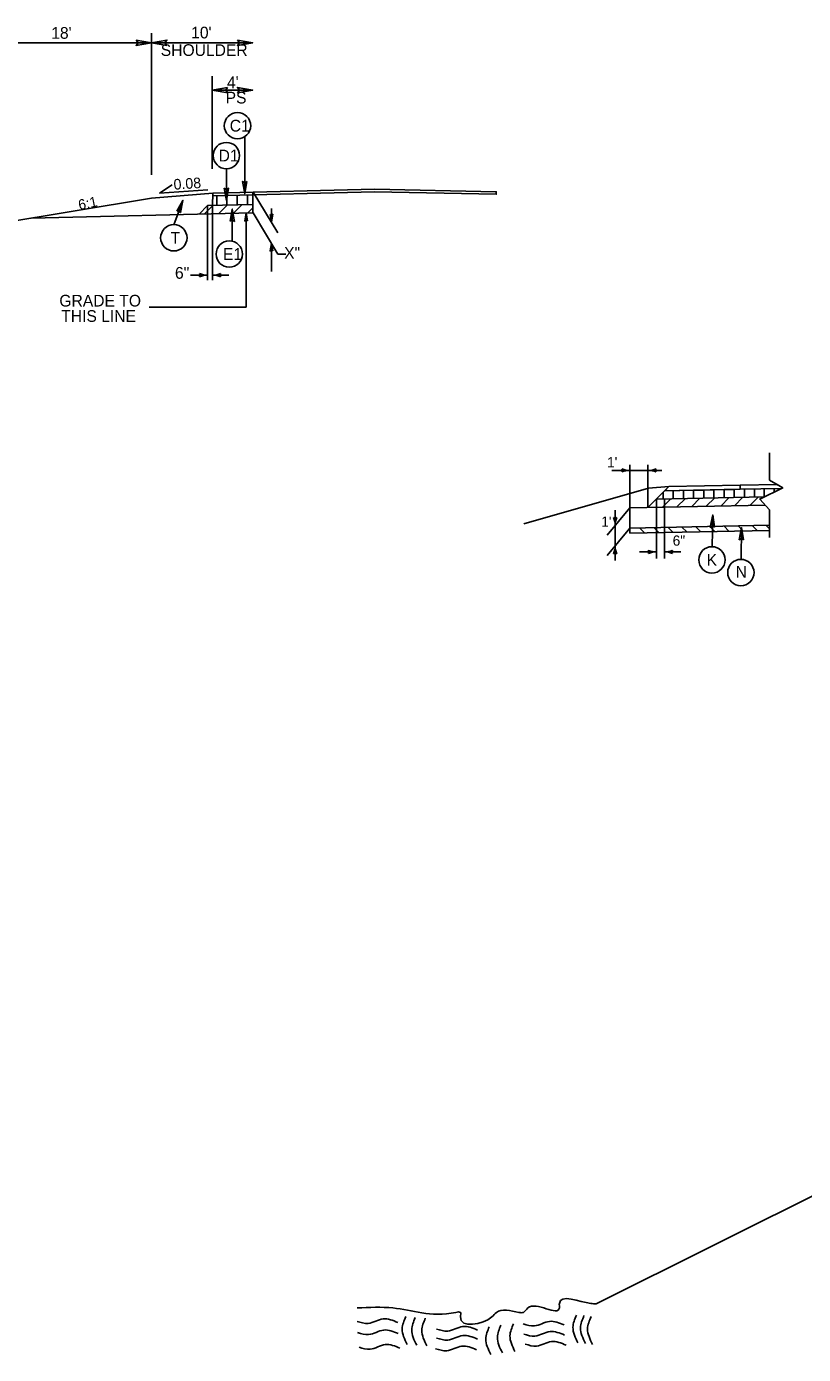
# Model space of a CAD drawing. Extents: x 2176024 to 2177225, y 75947 to 76635.
# Drawn here: x 2176544.3 to 2176620.9, y 76392.4 to 76523.4 of the extents above; entities that cross this region are included whole.
import ezdxf

# ---------------------------------------------------------------- set-up
doc = ezdxf.new("R2010")
doc.units = 0
for name, color, linetype in [('Old_Level_1', 7, 'Continuous'), ('Old_Level_10', 7, 'Continuous'), ('Old_Level_11', 7, 'Continuous'), ('Old_Level_2', 7, 'Continuous'), ('Prop Dimension', 7, 'Continuous'), ('Typical Curb CELL', 7, 'Continuous'), ('Typical Pavement Slope CELL', 7, 'Continuous'), ('Typical Pavement Slope Information CELL', 7, 'Continuous'), ('Typical Shoulder Slope CELL', 7, 'Continuous'), ('Typical Slope Point Local CELL', 7, 'Continuous'), ('Typical Terminator CELL', 7, 'Continuous'), ('Typical Text General CELL', 7, 'Continuous')]:
    doc.layers.add(name, color=color, linetype=linetype)

msp = doc.modelspace()

# ---------------------------------------------------------------- linework, layer by layer
at = {"layer": 'Old_Level_1'}
for p, q in [((2176563.01, 76505.76), (2176563.02, 76506.73)), ((2176564.01, 76505.8), (2176564.01, 76506.75)), ((2176565.02, 76505.82), (2176565.03, 76506.78)), ((2176566.04, 76505.85), (2176566.05, 76506.81)), ((2176561.8, 76504.93), (2176562.63, 76505.76)), ((2176563.21, 76504.99), (2176564.04, 76505.81)), ((2176564.65, 76505.02), (2176565.48, 76505.84)), ((2176566.09, 76505.04), (2176566.57, 76505.52)), ((2176606.96, 76476.01), (2176607.79, 76476.84)), ((2176607.04, 76476.82), (2176607.04, 76477.47)), ((2176608.04, 76476.84), (2176608.04, 76477.64)), ((2176608.4, 76476.04), (2176609.23, 76476.87)), ((2176609.04, 76476.86), (2176609.04, 76477.66)), ((2176609.85, 76476.07), (2176610.67, 76476.89)), ((2176610.04, 76476.88), (2176610.04, 76477.68)), ((2176611.04, 76476.9), (2176611.04, 76477.7)), ((2176611.29, 76476.1), (2176612.12, 76476.92)), ((2176612.04, 76476.92), (2176612.04, 76477.72)), ((2176612.73, 76476.12), (2176613.56, 76476.95)), ((2176613.04, 76476.94), (2176613.04, 76477.74)), ((2176614.04, 76476.96), (2176614.04, 76477.76)), ((2176614.07, 76476.15), (2176614.9, 76476.98)), ((2176615.06, 76476.98), (2176615.06, 76477.78)), ((2176615.58, 76476.18), (2176616.41, 76477.01)), ((2176616.03, 76477), (2176616.03, 76477.8)), ((2176617.01, 76477.02), (2176617.01, 76477.82)), ((2176617.97, 76477.49), (2176617.97, 76477.84)), ((2176606.11, 76473.99), (2176606.6, 76473.5)), ((2176607.49, 76474.02), (2176607.98, 76473.53)), ((2176608.88, 76474.05), (2176609.37, 76473.56)), ((2176610.26, 76474.07), (2176610.75, 76473.58)), ((2176611.65, 76474.1), (2176612.14, 76473.61)), ((2176613.04, 76474.13), (2176613.53, 76473.64)), ((2176614.42, 76474.16), (2176614.91, 76473.67)), ((2176615.81, 76474.19), (2176616.3, 76473.7)), ((2176617.2, 76474.21), (2176617.53, 76473.88)), ((2176603.74, 76473.52), (2176603.82, 76473.45)), ((2176604.72, 76473.96), (2176605.21, 76473.47))]:
    msp.add_line(p, q, dxfattribs=at)
at = {"layer": 'Old_Level_10'}
msp.add_line((2176600.43, 76397.41), (2176632.34, 76413.36), dxfattribs=at)
at = {"layer": 'Old_Level_11'}
for p, q in [((2176565.77, 76512.55), (2176565.77, 76506.94)), ((2176563.96, 76509.39), (2176563.96, 76506.26)), ((2176558.78, 76503.87), (2176559.67, 76506.27)), ((2176562.1, 76505.76), (2176562.1, 76498.39)), ((2176562.6, 76505.76), (2176562.6, 76498.39)), ((2176564.54, 76502.27), (2176564.54, 76505.41)), ((2176560.44, 76498.9), (2176562.1, 76498.9)), ((2176564.2, 76498.89), (2176562.6, 76498.89)), ((2176606.91, 76479.64), (2176601.96, 76479.64)), ((2176603.74, 76475.94), (2176603.74, 76480.19)), ((2176605.54, 76475.98), (2176605.54, 76480.19)), ((2176606.37, 76476.81), (2176606.37, 76470.94)), ((2176607.17, 76476.82), (2176607.17, 76470.94)), ((2176603.74, 76475.94), (2176601.51, 76473.24)), ((2176602.31, 76470.75), (2176602.31, 76475.7)), ((2176611.87, 76472.1), (2176611.93, 76475.24)), ((2176614.73, 76470.86), (2176614.78, 76473.99)), ((2176603.74, 76473.94), (2176601.51, 76471.23)), ((2176604.7, 76471.6), (2176606.37, 76471.6)), ((2176608.77, 76471.6), (2176607.17, 76471.6))]:
    msp.add_line(p, q, dxfattribs=at)
for points in [[(2176565.98, 76508.14), (2176565.77, 76506.94), (2176565.56, 76508.15), (2176565.77, 76508)], [(2176563.76, 76507.46), (2176563.96, 76506.26), (2176564.18, 76507.47), (2176563.96, 76507.31)], [(2176559.06, 76505.22), (2176559.67, 76506.27), (2176559.45, 76505.07), (2176559.3, 76505.29)], [(2176564.34, 76504.21), (2176564.54, 76505.41), (2176564.76, 76504.2), (2176564.54, 76504.35)], [(2176612.11, 76474.03), (2176611.93, 76475.24), (2176611.69, 76474.03), (2176611.91, 76474.18)], [(2176614.97, 76472.78), (2176614.78, 76473.99), (2176614.55, 76472.79), (2176614.76, 76472.93)]]:
    msp.add_lwpolyline(points, close=True, dxfattribs=at)
for centre in [(2176565.06, 76513.64), (2176563.96, 76510.69), (2176558.78, 76502.58), (2176564.25, 76500.98), (2176611.85, 76470.81), (2176614.7, 76469.56)]:
    msp.add_circle(centre, 1.3, dxfattribs=at)
for centre, radius, start, end in [((2176560.89, 76498.9), 0.448, 339.2343, 20.766), ((2176562.08, 76500.81), 1.92, 246.4848, 270.7622), ((2176562.08, 76496.98), 1.92, 89.2381, 113.5155), ((2176562.08, 76500.81), 1.94, 247.1893, 260.4638), ((2176562.08, 76496.98), 1.94, 99.5365, 112.811), ((2176562.08, 76500.81), 1.97, 247.7696, 256.6115), ((2176562.08, 76496.98), 1.97, 103.3888, 112.2307), ((2176562.08, 76500.81), 2, 248.2502, 253.7031), ((2176562.08, 76500.81), 2.02, 248.6472, 251.2913), ((2176562.08, 76496.98), 2, 106.2972, 111.7501), ((2176562.08, 76496.98), 2.02, 108.709, 111.3531), ((2176562.63, 76500.81), 1.92, 269.2382, 293.5156), ((2176562.63, 76496.98), 1.92, 66.4849, 90.7623), ((2176562.63, 76500.81), 1.94, 279.5367, 292.8111), ((2176562.63, 76496.98), 1.94, 67.1895, 80.4639), ((2176562.63, 76500.81), 1.97, 283.389, 292.2308), ((2176562.63, 76496.98), 1.97, 67.7698, 76.6116), ((2176562.63, 76500.81), 2, 286.2973, 291.7503), ((2176562.63, 76496.98), 2, 68.2503, 73.7032), ((2176562.63, 76500.81), 2.02, 288.7091, 291.3532), ((2176562.63, 76496.98), 2.02, 68.6473, 71.2914), ((2176563.81, 76498.89), 0.448, 159.2344, 200.7661), ((2176602.54, 76479.64), 0.448, 339.2343, 20.766), ((2176603.72, 76481.55), 1.92, 246.4848, 270.7622), ((2176603.72, 76477.72), 1.92, 89.2381, 113.5155), ((2176603.72, 76481.55), 1.94, 247.1893, 260.4638), ((2176603.72, 76481.55), 1.97, 247.7696, 256.6115), ((2176603.72, 76477.72), 1.94, 99.5365, 112.811), ((2176603.72, 76477.72), 1.97, 103.3888, 112.2307), ((2176603.72, 76481.55), 2, 248.2502, 253.7031), ((2176603.72, 76481.55), 2.02, 248.6472, 251.2913), ((2176603.72, 76477.72), 2, 106.2972, 111.7501), ((2176603.72, 76477.72), 2.02, 108.709, 111.3531), ((2176605.57, 76481.55), 1.92, 269.2382, 293.5156), ((2176605.57, 76477.72), 1.92, 66.4849, 90.7623), ((2176605.57, 76481.55), 1.94, 279.5367, 292.8111), ((2176605.57, 76477.72), 1.94, 67.1895, 80.4639), ((2176605.57, 76481.55), 1.97, 283.389, 292.2308), ((2176605.57, 76477.72), 1.97, 67.7698, 76.6116), ((2176605.57, 76481.55), 2, 286.2973, 291.7503), ((2176605.57, 76477.72), 2, 68.2503, 73.7032), ((2176605.57, 76481.55), 2.02, 288.7091, 291.3532), ((2176605.57, 76477.72), 2.02, 68.6473, 71.2914), ((2176606.75, 76479.64), 0.448, 159.2344, 200.7661), ((2176602.31, 76475.41), 0.448, 249.2342, 290.7658), ((2176600.39, 76474.23), 1.92, 359.2379, 23.5154), ((2176600.39, 76474.23), 1.94, 9.5364, 22.8108), ((2176600.39, 76474.23), 1.97, 13.3887, 22.2305), ((2176600.39, 76474.23), 2, 16.2971, 21.75), ((2176600.39, 76474.23), 2.02, 18.7088, 21.3529), ((2176604.22, 76474.23), 1.92, 156.4846, 180.7621), ((2176604.22, 76474.23), 1.94, 157.1892, 170.4636), ((2176604.22, 76474.23), 1.97, 157.7695, 166.6113), ((2176604.22, 76474.23), 2, 158.25, 163.7029), ((2176604.22, 76474.23), 2.02, 158.6471, 161.2912), ((2176600.39, 76472.18), 1.92, 336.4846, 0.7621), ((2176602.31, 76470.99), 0.448, 69.2342, 110.7658), ((2176600.39, 76472.18), 1.94, 337.1892, 350.4636), ((2176600.39, 76472.18), 1.97, 337.7695, 346.6113), ((2176600.39, 76472.18), 2, 338.25, 343.7029), ((2176600.39, 76472.18), 2.02, 338.6471, 341.2912), ((2176604.22, 76472.18), 1.92, 179.2379, 203.5153), ((2176604.22, 76472.18), 1.94, 189.5364, 202.8108), ((2176604.22, 76472.18), 1.97, 193.3887, 202.2305), ((2176604.22, 76472.18), 2, 196.2971, 201.75), ((2176604.22, 76472.18), 2.02, 198.7088, 201.3529), ((2176605.16, 76471.6), 0.448, 339.2343, 20.766), ((2176606.35, 76473.51), 1.92, 246.4848, 270.7622), ((2176606.35, 76469.68), 1.92, 89.2381, 113.5155), ((2176606.35, 76473.51), 1.94, 247.1893, 260.4638), ((2176606.35, 76469.68), 1.94, 99.5365, 112.811), ((2176606.35, 76473.51), 1.97, 247.7696, 256.6115), ((2176606.35, 76469.68), 1.97, 103.3888, 112.2307), ((2176606.35, 76473.51), 2, 248.2502, 253.7031), ((2176606.35, 76473.51), 2.02, 248.6472, 251.2913), ((2176606.35, 76469.68), 2, 106.2972, 111.7501), ((2176606.35, 76469.68), 2.02, 108.709, 111.3531), ((2176607.2, 76473.51), 1.92, 269.2382, 293.5156), ((2176607.2, 76469.68), 1.92, 66.4849, 90.7623), ((2176607.2, 76473.51), 1.94, 279.5367, 292.8111), ((2176607.2, 76469.68), 1.94, 67.1895, 80.4639), ((2176607.2, 76473.51), 1.97, 283.389, 292.2308), ((2176607.2, 76469.68), 1.97, 67.7698, 76.6116), ((2176607.2, 76473.51), 2, 286.2973, 291.7503), ((2176607.2, 76469.68), 2, 68.2503, 73.7032), ((2176607.2, 76473.51), 2.02, 288.7091, 291.3532), ((2176607.2, 76469.68), 2.02, 68.6473, 71.2914), ((2176608.38, 76471.6), 0.448, 159.2344, 200.7661)]:
    msp.add_arc(centre, radius, start, end, dxfattribs=at)
at = {"layer": 'Old_Level_2'}
for points in [[(2176600.43, 76397.41), (2176599.9, 76397.46), (2176596.8, 76397.46), (2176596.8, 76397.02), (2176593.69, 76397.02), (2176593.25, 76396.58), (2176592.8, 76396.58), (2176590.59, 76396.58), (2176590.14, 76396.13), (2176587.04, 76396.13), (2176587.04, 76396.58), (2176586.6, 76396.58), (2176580.39, 76397.02), (2176576.85, 76397.02)], [(2176580.87, 76395.59), (2176579.43, 76395.93), (2176577.94, 76395.49), (2176576.85, 76395.69)], [(2176581.65, 76396.16), (2176581.3, 76394.96), (2176581.79, 76393.42)], [(2176582.59, 76396.06), (2176582.24, 76394.87), (2176582.74, 76393.33)], [(2176583.58, 76396.01), (2176583.24, 76394.82), (2176583.73, 76393.28)], [(2176592.28, 76395.46), (2176591.93, 76394.27), (2176592.42, 76392.73)], [(2176597.27, 76395.34), (2176595.83, 76395.69), (2176594.34, 76395.24), (2176593.24, 76395.44)], [(2176598.49, 76396.31), (2176598.14, 76395.11), (2176598.63, 76393.57)], [(2176599.23, 76396.26), (2176598.88, 76395.06), (2176599.38, 76393.52)], [(2176599.93, 76396.16), (2176599.58, 76394.96), (2176600.07, 76393.42)], [(2176580.92, 76394.49), (2176579.48, 76394.84), (2176577.99, 76394.39), (2176576.9, 76394.59)], [(2176588.72, 76394.84), (2176587.28, 76395.19), (2176585.79, 76394.74), (2176584.7, 76394.94)], [(2176588.72, 76393.95), (2176587.28, 76394.29), (2176585.79, 76393.85), (2176584.7, 76394.05)], [(2176589.89, 76395.16), (2176589.54, 76393.97), (2176590.04, 76392.43)], [(2176591.03, 76395.31), (2176590.69, 76394.12), (2176591.18, 76392.58)], [(2176597.32, 76394.34), (2176595.88, 76394.69), (2176594.39, 76394.24), (2176593.29, 76394.44)], [(2176581.07, 76393.05), (2176579.63, 76393.4), (2176578.14, 76392.95), (2176577.05, 76393.15)], [(2176588.62, 76392.9), (2176587.18, 76393.25), (2176585.69, 76392.8), (2176584.6, 76393)], [(2176597.47, 76393.35), (2176596.03, 76393.7), (2176594.54, 76393.25), (2176593.44, 76393.45)]]:
    msp.add_spline(points, degree=3, dxfattribs=at)
at = {"layer": 'Prop Dimension'}
for p, q in [((2176556.57, 76508.79), (2176556.57, 76522.77)), ((2176556.57, 76521.82), (2176538.57, 76521.82)), ((2176566.57, 76521.82), (2176556.57, 76521.82)), ((2176562.57, 76509.39), (2176562.57, 76518.54)), ((2176566.57, 76517.15), (2176562.57, 76517.15)), ((2176566.62, 76507.07), (2176569.05, 76503.06)), ((2176568.41, 76504.14), (2176568.41, 76505.46)), ((2176568.41, 76504.14), (2176568.41, 76505.46)), ((2176565.91, 76505), (2176565.91, 76497.13)), ((2176565.91, 76504.36), (2176565.91, 76495.73)), ((2176566.62, 76505.05), (2176569.05, 76500.96)), ((2176566.62, 76505.05), (2176569.05, 76500.96)), ((2176568.41, 76499.26), (2176568.41, 76502.03)), ((2176568.41, 76499.26), (2176568.41, 76502.03)), ((2176569.83, 76500.96), (2176569.05, 76500.96)), ((2176569.83, 76500.96), (2176569.05, 76500.96)), ((2176556.34, 76495.73), (2176565.91, 76495.73))]:
    msp.add_line(p, q, dxfattribs=at)
at = {"layer": 'Typical Curb CELL'}
for p, q in [((2176566.57, 76505.05), (2176566.57, 76507.07)), ((2176544.7, 76504.51), (2176566.57, 76505.05))]:
    msp.add_line(p, q, dxfattribs=at)
at = {"layer": 'Typical Pavement Slope CELL'}
for p, q in [((2176562.61, 76506.97), (2176562.6, 76505.76)), ((2176522.57, 76500.82), (2176556.57, 76506.49)), ((2176562.1, 76505.75), (2176561.27, 76504.92)), ((2176566.57, 76505.86), (2176562.1, 76505.75)), ((2176607.6, 76478.04), (2176605.54, 76475.98)), ((2176607.6, 76478.04), (2176614.64, 76478.18)), ((2176614.64, 76477.77), (2176614.64, 76478.18)), ((2176617.02, 76477.02), (2176606.37, 76476.81)), ((2176614.64, 76477.77), (2176607.19, 76477.62)), ((2176617.1, 76476.21), (2176603.74, 76475.94)), ((2176603.74, 76475.94), (2176603.74, 76473.44)), ((2176617.53, 76474.22), (2176603.74, 76473.94)), ((2176617.54, 76473.72), (2176603.74, 76473.44))]:
    msp.add_line(p, q, dxfattribs=at)
at = {"layer": 'Typical Pavement Slope Information CELL'}
for q in [(2176558.6, 76507.81), (2176562.13, 76507.3)]:
    msp.add_line((2176557.38, 76506.99), q, dxfattribs=at)
at = {"layer": 'Typical Shoulder Slope CELL'}
for p, q in [((2176562.61, 76506.97), (2176556.57, 76506.49)), ((2176566.57, 76505.86), (2176562.1, 76505.75)), ((2176607.6, 76478.04), (2176605.6, 76477.88)), ((2176593.29, 76474.36), (2176605.6, 76477.88)), ((2176616.57, 76476.8), (2176617.53, 76475.74))]:
    msp.add_line(p, q, dxfattribs=at)
msp.add_lwpolyline([(2176617.53, 76473.01), (2176617.53, 76475.74), (2176616.57, 76476.8), (2176618.84, 76477.91), (2176617.53, 76478.68), (2176617.53, 76481.37)], dxfattribs=at)
at = {"layer": 'Typical Slope Point Local CELL'}
for p, q in [((2176607.6, 76478.04), (2176607.19, 76477.62)), ((2176614.64, 76478.18), (2176607.6, 76478.04)), ((2176618.27, 76478.25), (2176614.64, 76478.18)), ((2176614.64, 76477.77), (2176614.64, 76478.18)), ((2176614.64, 76478.18), (2176614.64, 76477.77)), ((2176614.64, 76477.77), (2176618.72, 76477.86))]:
    msp.add_line(p, q, dxfattribs=at)
msp.add_lwpolyline([(2176562.61, 76506.97), (2176578.57, 76507.37), (2176590.57, 76507.12), (2176590.57, 76506.87), (2176578.57, 76507.12), (2176562.61, 76506.72)], close=True, dxfattribs=at)
for points in [[(2176618.72, 76477.86), (2176618.84, 76477.91), (2176618.27, 76478.25)], [(2176607.19, 76477.62), (2176610.04, 76477.68), (2176611.04, 76477.7)], [(2176611.04, 76477.7), (2176612.04, 76477.72), (2176613.04, 76477.74), (2176614.04, 76477.76), (2176614.64, 76477.77)]]:
    msp.add_lwpolyline(points, dxfattribs=at)
at = {"layer": 'Typical Terminator CELL'}
for points in [[(2176555.06, 76522.08), (2176556.57, 76521.82), (2176555.05, 76521.55), (2176555.25, 76521.82)], [(2176558.08, 76521.56), (2176556.57, 76521.82), (2176558.09, 76522.08), (2176557.9, 76521.82)], [(2176565.06, 76522.08), (2176566.57, 76521.82), (2176565.05, 76521.55), (2176565.25, 76521.82)], [(2176564.08, 76517.41), (2176562.57, 76517.15), (2176564.09, 76516.88), (2176563.9, 76517.15)], [(2176564.08, 76517.41), (2176562.57, 76517.15), (2176564.09, 76516.88), (2176563.9, 76517.15)], [(2176565.06, 76516.89), (2176566.57, 76517.15), (2176565.05, 76517.42), (2176565.25, 76517.15)], [(2176565.06, 76516.89), (2176566.57, 76517.15), (2176565.05, 76517.42), (2176565.25, 76517.15)], [(2176566.04, 76504.24), (2176565.91, 76505), (2176565.78, 76504.24), (2176565.91, 76504.33)], [(2176568.28, 76504.89), (2176568.41, 76504.14), (2176568.54, 76504.9), (2176568.41, 76504.8)], [(2176568.28, 76504.89), (2176568.41, 76504.14), (2176568.54, 76504.9), (2176568.41, 76504.8)], [(2176568.54, 76501.28), (2176568.41, 76502.03), (2176568.28, 76501.28), (2176568.41, 76501.37)], [(2176568.54, 76501.28), (2176568.41, 76502.03), (2176568.28, 76501.28), (2176568.41, 76501.37)]]:
    msp.add_lwpolyline(points, close=True, dxfattribs=at)

# ---------------------------------------------------------------- texts
at = {"layer": 'Old_Level_11'}
for s, height, rotation, p in [('C1', 1.16, 0.0003, (2176564.29, 76513.06)), ('D1', 1.16, 0.0003, (2176563.19, 76510.11)), ('T', 1.16, 0.0003, (2176558.45, 76502)), ('E1', 1.16, 0.0003, (2176563.62, 76500.4)), ('6"', 1.16, 0.0002, (2176558.89, 76498.54)), ("1'", 1.006, 0.0002, (2176601.51, 76479.94)), ("1'", 1.006, 0.0002, (2176600.93, 76474.08)), ('6"', 1.006, 0.0002, (2176607.98, 76472.21)), ('K', 1.16, 0, (2176611.32, 76470.23)), ('N', 1.16, 0, (2176614.18, 76469.05))]:
    msp.add_text(s, height=height, rotation=rotation, dxfattribs=at).set_placement(p)
msp.add_text('X"', height=1.153, dxfattribs=at).set_placement((2176569.66, 76500.51))
at = {"layer": 'Typical Pavement Slope Information CELL'}
msp.add_text('0.08', height=1.043, rotation=3.7801, dxfattribs=at).set_placement((2176558.79, 76507.32))
at = {"layer": 'Typical Slope Point Local CELL'}
msp.add_text('6:1', height=1.006, rotation=11.4865, dxfattribs=at).set_placement((2176549.47, 76505.32))
at = {"layer": 'Typical Text General CELL'}
for s, p in [("18' ", (2176546.69, 76522.21)), ("10' ", (2176560.49, 76522.25)), ('SHOULDER', (2176557.49, 76520.52)), ("4'", (2176564.02, 76517.34)), ('PS', (2176563.89, 76515.83)), ('GRADE TO', (2176547.49, 76495.8)), (' THIS LINE', (2176547.25, 76494.29))]:
    msp.add_text(s, height=1.153, dxfattribs=at).set_placement(p)

doc.saveas('drawing.dxf')
